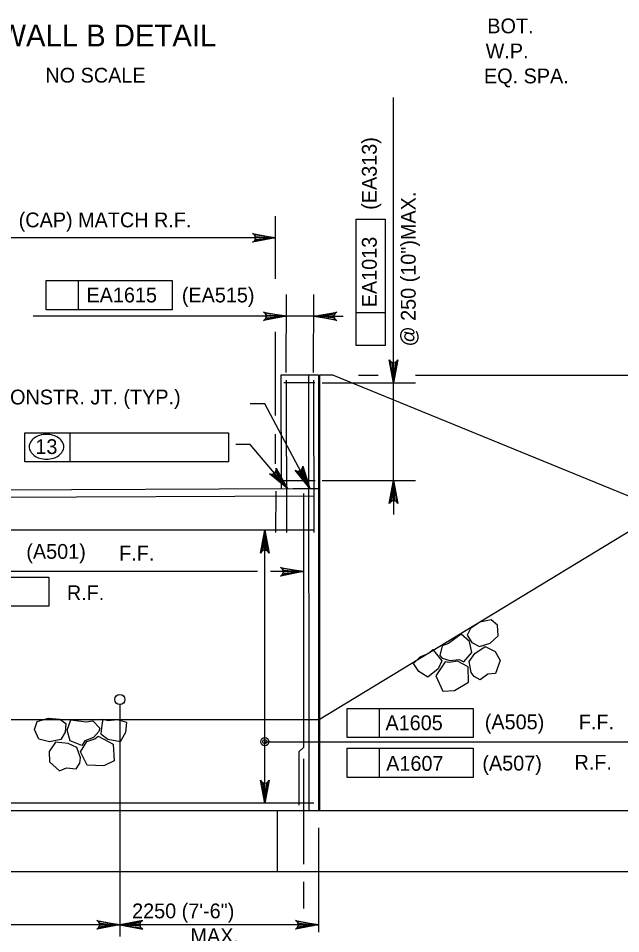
# Model space of a CAD drawing. Extents: x 638340 to 640241, y 295465 to 298435.
# Drawn here: x 638823.8 to 638945.8, y 297348.7 to 297534.2 of the extents above; entities that cross this region are included whole.
import ezdxf

# ---------------------------------------------------------------- set-up
doc = ezdxf.new("R2010")
doc.units = 0
for name, color, linetype in [('10', 7, 'Continuous'), ('3', 7, 'Continuous'), ('4', 7, 'Continuous'), ('5', 7, 'Continuous')]:
    doc.layers.add(name, color=color, linetype=linetype)

# ---------------------------------------------------------------- blocks, each defined once
blk = doc.blocks.new('ROCK')
at = {"layer": '4'}
for points in [[(2.36725, 1.088), (2.2065, 0.82625), (2.378625, 0.506625), (2.66975, 0.3095), (3.128875, 0.403375), (3.48475, 0.6775), (3.4915, 1.123375), (3.25625, 1.36725), (2.783625, 1.308375)], [(1.10175, -0.02725), (1.4015, -0.159125), (1.78825, -0.148875), (1.980875, -0.266), (2.343375, 0.09475), (2.27875, 0.5505), (1.969375, 0.883), (1.4225, 0.553625), (1.152875, 0.479), (1.0105, 0.082)], [(0.74675, 0.359875), (0.882, 0.16), (1.072875, -0.144), (0.892, -0.457375), (0.448125, -0.758625), (0.1, -0.49325), (-0.095, -0.146375), (0.202875, 0.1025), (0.579125, 0.219875)], [(2.231375, -0.71725), (2.2025, -0.266375), (2.45475, 0.037125), (2.9085, 0.28875), (3.2995, 0.047625), (3.46875, -0.344), (3.231625, -0.855), (2.92, -0.860375), (2.5765, -1.054625), (2.340375, -0.904375)], [(1.2085, -0.192875), (0.778375, -0.737625), (1.008375, -1.391375), (1.48725, -1.396875), (2.09825, -1.106625), (2.133375, -0.486375), (1.723125, -0.203375), (1.37425, -0.239875)]]:
    blk.add_lwpolyline(points, close=True, dxfattribs=at)

msp = doc.modelspace()

# ---------------------------------------------------------------- linework, layer by layer
at = {"layer": '10'}
for p, q in [((638876.94, 297461.87), (638877, 297438.92)), ((638884.58, 297461.87), (638876.94, 297461.87)), ((638882.55, 297461.87), (638882.61, 297373.59)), ((638884.58, 297461.87), (638884.58, 297373.59)), ((638884.8, 297461.87), (638884.8, 297373.59)), ((638887.46, 297461.87), (638884.8, 297461.87)), ((638951.39, 297435.73), (638887.46, 297461.87)), ((638876.95, 297449.89), (638877.01, 297449.85)), ((638662.42, 297438), (638879.47, 297438.93)), ((638879.47, 297438.93), (638884.69, 297438.95)), ((638884.58, 297392.05), (638951.39, 297432.65)), ((638883.15, 297392.05), (638653.79, 297392.05)), ((638884.69, 297392.05), (638881.11, 297392.05)), ((638954.47, 297373.59), (638806.35, 297373.59)), ((638876.21, 297373.59), (638876.21, 297361.29)), ((638573.23, 297361.29), (638954.47, 297361.29))]:
    msp.add_line(p, q, dxfattribs=at)
at = {"layer": '3'}
for p, q in [((638899.79, 297460.34), (638899.79, 297518.16)), ((638875.9, 297481.39), (638875.9, 297494.12)), ((638892.19, 297467.92), (638892.19, 297493.46)), ((638892.19, 297493.46), (638898.09, 297493.46)), ((638898.09, 297493.46), (638898.09, 297467.92)), ((638875.9, 297489.7), (638773.53, 297489.7)), ((638829.41, 297481.05), (638854.95, 297481.05)), ((638829.41, 297475.15), (638829.41, 297481.05)), ((638836.01, 297475.15), (638836.01, 297481.05)), ((638854.95, 297481.05), (638854.95, 297475.15)), ((638878.04, 297462.4), (638878.1, 297478.25)), ((638883.6, 297462.39), (638883.66, 297478.24)), ((638854.95, 297475.15), (638829.41, 297475.15)), ((638856.52, 297473.81), (638826.83, 297473.81)), ((638878.08, 297473.81), (638849.87, 297473.81)), ((638883.66, 297473.81), (638878.08, 297473.81)), ((638883.65, 297473.81), (638889.57, 297473.81)), ((638898.09, 297474.51), (638892.19, 297474.51)), ((638875.9, 297453.72), (638875.9, 297470.65)), ((638898.09, 297467.92), (638892.19, 297467.92)), ((638899.79, 297463.29), (638899.79, 297466.24)), ((638892.72, 297461.87), (638896.66, 297461.87)), ((638904.2, 297461.87), (639036.38, 297461.87)), ((638885.34, 297460.34), (638904.22, 297460.34)), ((638899.79, 297439.54), (638899.79, 297460.34)), ((638873.69, 297456.07), (638870.74, 297456.07)), ((638882.82, 297438.94), (638873.69, 297456.07)), ((638825.12, 297450.22), (638834.3, 297450.22)), ((638825.12, 297444.31), (638825.12, 297450.22)), ((638834.3, 297444.31), (638834.3, 297450.22)), ((638834.3, 297450.22), (638866.33, 297450.22)), ((638866.33, 297450.22), (638866.33, 297444.31)), ((638875.9, 297443.91), (638875.9, 297449.9)), ((638870.78, 297447.85), (638867.82, 297447.85)), ((638878.33, 297438.92), (638870.78, 297447.85)), ((638866.33, 297444.31), (638825.12, 297444.31)), ((638885.34, 297440.54), (638904.22, 297440.54)), ((638899.79, 297439.54), (638899.79, 297433.63)), ((638873.72, 297402.84), (638873.72, 297430.5)), ((638872.22, 297422.07), (638772.47, 297422.07)), ((638881.56, 297422.07), (638874.88, 297422.07)), ((638804.42, 297420.98), (638829.96, 297420.98)), ((638829.96, 297420.98), (638829.96, 297415.08)), ((638829.96, 297415.08), (638804.42, 297415.08)), ((638873.72, 297375.13), (638873.72, 297403.63)), ((638890.37, 297394.37), (638915.91, 297394.37)), ((638890.37, 297388.47), (638890.37, 297394.37)), ((638896.96, 297388.47), (638896.96, 297394.37)), ((638915.91, 297394.37), (638915.91, 297388.47)), ((638915.91, 297388.47), (638890.37, 297388.47)), ((638873.72, 297387.59), (638948.93, 297387.59)), ((638890.37, 297380.39), (638890.37, 297386.29)), ((638890.37, 297386.29), (638915.91, 297386.29)), ((638896.96, 297380.39), (638896.96, 297386.29)), ((638915.91, 297386.29), (638915.91, 297380.39)), ((638915.91, 297380.39), (638890.37, 297380.39)), ((638884.58, 297370.15), (638884.58, 297349.04)), ((638881.56, 297359.22), (638881.56, 297353.8)), ((638884.58, 297350.53), (638603.67, 297350.53))]:
    msp.add_line(p, q, dxfattribs=at)
for points in [[(638875.9, 297489.7), (638871.24, 297488.82), (638871.6, 297489.07), (638871.79, 297489.38), (638871.84, 297489.7), (638871.79, 297490.01), (638871.6, 297490.32), (638871.24, 297490.57), (638875.9, 297489.7), (638871.6, 297490.32), (638871.79, 297490.01), (638875.9, 297489.7), (638871.84, 297489.7), (638871.79, 297489.38), (638875.9, 297489.7), (638871.6, 297489.07)], [(638878.08, 297473.81), (638873.42, 297472.93), (638873.78, 297473.18), (638873.97, 297473.49), (638874.02, 297473.81), (638873.97, 297474.12), (638873.78, 297474.43), (638873.42, 297474.68), (638878.08, 297473.81), (638873.78, 297474.43), (638873.97, 297474.12), (638878.08, 297473.81), (638874.02, 297473.81), (638873.97, 297473.49), (638878.08, 297473.81), (638873.78, 297473.18)], [(638883.65, 297473.81), (638888.31, 297474.68), (638887.95, 297474.43), (638887.76, 297474.12), (638887.71, 297473.81), (638887.76, 297473.49), (638887.95, 297473.18), (638888.31, 297472.93), (638883.65, 297473.81), (638887.95, 297473.18), (638887.76, 297473.49), (638883.65, 297473.81), (638887.71, 297473.81), (638887.76, 297474.12), (638883.65, 297473.81), (638887.95, 297474.43)], [(638899.79, 297460.34), (638898.92, 297465), (638899.17, 297464.64), (638899.48, 297464.45), (638899.79, 297464.4), (638900.11, 297464.45), (638900.42, 297464.64), (638900.67, 297465), (638899.79, 297460.34), (638900.42, 297464.64), (638900.11, 297464.45), (638899.79, 297460.34), (638899.79, 297464.4), (638899.48, 297464.45), (638899.79, 297460.34), (638899.17, 297464.64)], [(638882.82, 297438.94), (638879.85, 297442.64), (638880.24, 297442.44), (638880.61, 297442.43), (638880.91, 297442.53), (638881.16, 297442.72), (638881.35, 297443.03), (638881.4, 297443.47), (638882.82, 297438.94), (638881.35, 297443.03), (638881.16, 297442.72), (638882.82, 297438.94), (638880.91, 297442.53), (638880.61, 297442.43), (638882.82, 297438.94), (638880.24, 297442.44)], [(638878.33, 297438.92), (638874.65, 297441.92), (638875.07, 297441.8), (638875.43, 297441.86), (638875.71, 297442.02), (638875.91, 297442.27), (638876.03, 297442.61), (638875.99, 297443.05), (638878.33, 297438.92), (638876.03, 297442.61), (638875.91, 297442.27), (638878.33, 297438.92), (638875.71, 297442.02), (638875.43, 297441.86), (638878.33, 297438.92), (638875.07, 297441.8)], [(638899.79, 297440.54), (638900.67, 297435.88), (638900.42, 297436.24), (638900.11, 297436.42), (638899.79, 297436.48), (638899.48, 297436.42), (638899.17, 297436.24), (638898.92, 297435.88), (638899.79, 297440.54), (638899.17, 297436.24), (638899.48, 297436.42), (638899.79, 297440.54), (638899.79, 297436.48), (638900.11, 297436.42), (638899.79, 297440.54), (638900.42, 297436.24)], [(638873.72, 297430.5), (638874.59, 297425.84), (638874.34, 297426.2), (638874.03, 297426.38), (638873.72, 297426.44), (638873.4, 297426.38), (638873.09, 297426.2), (638872.84, 297425.84), (638873.72, 297430.5), (638873.09, 297426.2), (638873.4, 297426.38), (638873.72, 297430.5), (638873.72, 297426.44), (638874.03, 297426.38), (638873.72, 297430.5), (638874.34, 297426.2)], [(638881.56, 297422.07), (638876.9, 297421.19), (638877.26, 297421.44), (638877.45, 297421.75), (638877.5, 297422.07), (638877.45, 297422.38), (638877.26, 297422.69), (638876.9, 297422.94), (638881.56, 297422.07), (638877.26, 297422.69), (638877.45, 297422.38), (638881.56, 297422.07), (638877.5, 297422.07), (638877.45, 297421.75), (638881.56, 297422.07), (638877.26, 297421.44)], [(638873.72, 297375.13), (638872.84, 297379.79), (638873.09, 297379.43), (638873.4, 297379.25), (638873.72, 297379.19), (638874.03, 297379.25), (638874.34, 297379.43), (638874.59, 297379.79), (638873.72, 297375.13), (638874.34, 297379.43), (638874.03, 297379.25), (638873.72, 297375.13), (638873.72, 297379.19), (638873.4, 297379.25), (638873.72, 297375.13), (638873.09, 297379.43)]]:
    msp.add_lwpolyline(points, dxfattribs=at)
for points in [[(638886.62, 297474.3), (638886.62, 297473.32), (638883.66, 297473.81)], [(638899.3, 297463.29), (638900.29, 297463.29), (638899.79, 297460.34)], [(638876.05, 297440.86), (638876.8, 297441.5), (638878.33, 297438.92)], [(638880.99, 297441.32), (638881.86, 297441.78), (638882.82, 297438.94)], [(638874.21, 297427.55), (638873.22, 297427.55), (638873.72, 297430.5)], [(638874.21, 297378.09), (638873.22, 297378.09), (638873.72, 297375.13)]]:
    msp.add_lwpolyline(points, close=True, dxfattribs=at)
for centre, radius in [((638844.34, 297396.15), 1.03), ((638873.72, 297387.63), 0.833), ((638873.72, 297387.63), 0.417)]:
    msp.add_circle(centre, radius, dxfattribs=at)
for centre, radius, start, end in [((638828.63, 297446.9), 2.76, 125.6316, 149.9767), ((638829.16, 297446.17), 3.66, 106.5358, 125.6316), ((638829.5, 297445.01), 4.87, 90, 106.5358), ((638829.5, 297445.01), 4.87, 73.4642, 90), ((638829.85, 297446.17), 3.66, 54.3684, 73.4642), ((638830.37, 297446.9), 2.76, 30.0233, 54.3684), ((638827.83, 297447.37), 1.83, 149.9767, 180), ((638827.83, 297447.37), 1.83, 180, 210.0233), ((638831.18, 297447.37), 1.83, 0, 30.0233), ((638831.18, 297447.37), 1.83, 329.9767, 0), ((638828.63, 297447.84), 2.76, 210.0233, 234.3684), ((638829.16, 297448.57), 3.66, 234.3684, 253.4642), ((638829.85, 297448.57), 3.66, 286.5358, 305.6316), ((638830.37, 297447.84), 2.76, 305.6316, 329.9767), ((638829.5, 297449.73), 4.87, 253.4642, 270), ((638829.5, 297449.73), 4.87, 270, 286.5358)]:
    msp.add_arc(centre, radius, start, end, dxfattribs=at)
at = {"layer": '4'}
for points in [[(638844.34, 297350.53), (638839.68, 297349.66), (638840.04, 297349.91), (638840.22, 297350.22), (638840.28, 297350.53), (638840.22, 297350.85), (638840.04, 297351.16), (638839.68, 297351.41), (638844.34, 297350.53), (638840.04, 297351.16), (638840.22, 297350.85), (638844.34, 297350.53), (638840.28, 297350.53), (638840.22, 297350.22), (638844.34, 297350.53), (638840.04, 297349.91)], [(638844.34, 297350.53), (638849, 297349.66), (638848.64, 297349.91), (638848.46, 297350.22), (638848.4, 297350.53), (638848.46, 297350.85), (638848.64, 297351.16), (638849, 297351.41), (638844.34, 297350.53), (638848.64, 297351.16), (638848.46, 297350.85), (638844.34, 297350.53), (638848.4, 297350.53), (638848.46, 297350.22), (638844.34, 297350.53), (638848.64, 297349.91)], [(638884.58, 297350.53), (638879.91, 297349.66), (638880.27, 297349.91), (638880.46, 297350.22), (638880.51, 297350.53), (638880.46, 297350.85), (638880.27, 297351.16), (638879.91, 297351.41), (638884.58, 297350.53), (638880.27, 297351.16), (638880.46, 297350.85), (638884.58, 297350.53), (638880.51, 297350.53), (638880.46, 297350.22), (638884.58, 297350.53), (638880.27, 297349.91)]]:
    msp.add_lwpolyline(points, dxfattribs=at)
at = {"layer": '5'}
for p, q in [((638883.86, 297460.34), (638877.6, 297460.34)), ((638878.03, 297460.84), (638878.1, 297429.98)), ((638883.6, 297460.85), (638883.66, 297429.99)), ((638877.6, 297440.54), (638883.92, 297440.54)), ((638875.92, 297438.38), (638875.9, 297429.98)), ((638881.56, 297437.92), (638881.56, 297386.47)), ((638772.91, 297436.94), (638883.66, 297437.41)), ((638883.66, 297430.5), (638773.01, 297430.5)), ((638844.34, 297395.13), (638844.34, 297348.15)), ((638881.56, 297386.47), (638880.63, 297385.53)), ((638880.63, 297385.53), (638880.63, 297374.75)), ((638881.56, 297384.14), (638881.56, 297362.83)), ((638883.66, 297375.13), (638809.71, 297375.13))]:
    msp.add_line(p, q, dxfattribs=at)

# ---------------------------------------------------------------- block references
at = {"layer": '3'}
for p, xscale, yscale, rotation in [((638904.22, 297404.2), 4.921475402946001, 4.921475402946, 5.152771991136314), ((638845.02, 297391.99), 4.921475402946, -4.921475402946, -156.2166383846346)]:
    msp.add_blockref('ROCK', p, dxfattribs=dict(at, xscale=xscale, yscale=yscale, rotation=rotation))

# ---------------------------------------------------------------- texts
for s, height, p in [('BOT.', 3, (638918.78, 297531.15)), ('CHEEKWALL B DETAIL', 4.4294, (638799.36, 297528.49)), ('W.P.', 3, (638918.44, 297526.08)), ('NO SCALE', 3, (638829.28, 297521.16)), ('EQ. SPA.', 3, (638918.1, 297521.01)), ('(CAP) MATCH R.F.', 3.0001, (638823.87, 297491.84)), ('EA1615', 3, (638837.6, 297476.63)), ('(EA515)', 3, (638856.91, 297476.63)), ('CONSTR. JT. (TYP.)', 3.0001, (638819.23, 297455.95)), ('13', 3, (638827.25, 297445.91)), ('(A501)', 3, (638825.42, 297424.67)), ('F.F.', 3, (638844.21, 297424.33)), ('R.F.', 3, (638833.63, 297416.3)), ('(A505)', 3, (638918.27, 297390.13)), ('A1605', 3, (638898.15, 297389.95)), ('F.F.', 3, (638937.3, 297390.1)), ('A1607', 3, (638898.3, 297381.72)), ('(A507)', 3, (638917.78, 297381.78)), ('R.F.', 3, (638936.44, 297381.95)), ('2250 (7\'-6")', 3.0001, (638846.84, 297351.83)), ('MAX.', 3, (638858.67, 297346.83))]:
    msp.add_text(s, height=height, dxfattribs=at).set_placement(p)
for s, height, p in [('(EA313)', 3, (638896.38, 297495.39)), ('@ 250 (10")MAX.', 3.0001, (638904.27, 297467.7)), ('EA1013', 3, (638896.38, 297475.65))]:
    msp.add_text(s, height=height, rotation=90, dxfattribs=at).set_placement(p)

doc.saveas('drawing.dxf')
